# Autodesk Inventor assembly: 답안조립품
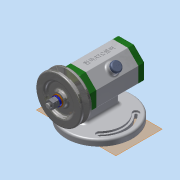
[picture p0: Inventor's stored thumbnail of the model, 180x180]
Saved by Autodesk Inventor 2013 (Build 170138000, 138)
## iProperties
Created: 2017-06
Part Number: 답안조립품
Document SubType Name: Assembly
Designer: Administrator
Author: Administrator
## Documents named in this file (14)
- C:\Users\Administrator\Desktop\470608V1020\답안조립품.iam
- C:\Users\Administrator\Desktop\470608V1020\1-본체.ipt
- C:\Users\Administrator\Desktop\470608V1020\베어링 15 x 32 x 9.ipt
- C:\Users\Administrator\Desktop\470608V1020\뒤커버.ipt
- C:\Users\Administrator\Desktop\470608V1020\앞커버.ipt
- C:\Users\Administrator\Desktop\470608V1020\오일 실 15 25 7.ipt
- C:\Users\Administrator\Desktop\470608V1020\축.ipt
- C:\Users\Administrator\Desktop\470608V1020\V벨트풀리.ipt
- C:\Users\Administrator\Desktop\470608V1020\고무캡.ipt
- C:\Users\Administrator\Desktop\470608V1020\스프링와셔 8.ipt
- C:\Users\Administrator\Desktop\470608V1020\와셔 8x17.ipt
- C:\Users\Administrator\Desktop\470608V1020\키 3 x 3 x 12.ipt
- C:\Users\Administrator\Desktop\470608V1020\너트 M 8.ipt
- C:\Users\Administrator\Desktop\470608V1020\볼트 M4 x 12.ipt
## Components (3 placed, 3 different names)
1. 1-본체:1
2. V벨트풀리:1
3. 고무캡:1
